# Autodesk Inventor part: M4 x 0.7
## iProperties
IsCustomPart: 0
Created: 2015-10
Part Number: M4 x 0.7
Material: 강, 연강
Description: 6각머리 태핑 나사
Document SubType Name: Modeling
Standard: KS B 1003
Designer: mdu
Standards Organization: KS
Language: ko-KR
Size Designation: M 4 x 25
Categories: <MemberInstance><Categories><Category DisplayName="조임쇠" InternalName="e4da775c-781d-43d5-af7c-5136215cf5a6" Mnemonic="FSTN"><Category DisplayName="볼트" InternalN
Density: 1 g/cm^3
Author: mdu
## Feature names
1. Fillet2
